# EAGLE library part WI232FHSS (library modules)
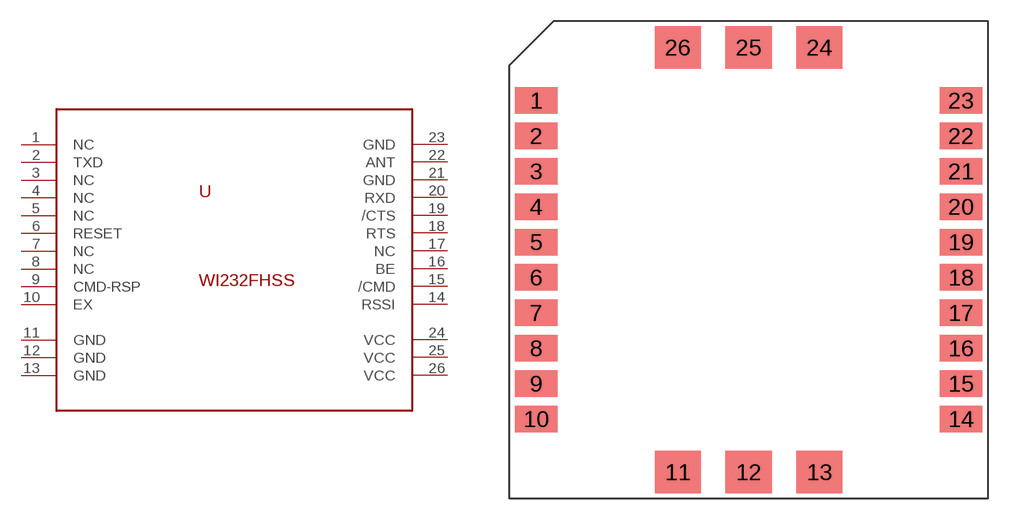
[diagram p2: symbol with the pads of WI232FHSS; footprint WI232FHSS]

Designator prefix U

## WI232FHSS  [WI232FHSS]
1  NC  nc
2  TXD  out
3  NC  nc
4  NC  nc
5  NC  nc
6  RESET  in
7  NC  nc
8  NC  nc
9  CMD-RSP  out
10  EX  out
11  GND  pwr
12  GND  pwr
13  GND  pwr
14  RSSI  out
15  /CMD  in
16  BE  out
17  NC  nc
18  RTS  in
19  /CTS  out
20  RXD  in
21  GND  pwr
22  ANT  out
23  GND  pwr
24  VCC  pwr
25  VCC  pwr
26  VCC  pwr

## Footprint WI232FHSS (pad centres in mm)
smd 3.048 x 1.905: 1 -15.24,11.43; 2 -15.24,8.89; 3 -15.24,6.35; 4 -15.24,3.81; 5 -15.24,1.27; 6 -15.24,-1.27; 7 -15.24,-3.81; 8 -15.24,-6.35; 9 -15.24,-8.89; 10 -15.24,-11.43; 14 15.24,-11.43; 15 15.24,-8.89; 16 15.24,-6.35; 17 15.24,-3.81; 18 15.24,-1.27; 19 15.24,1.27; 20 15.24,3.81; 21 15.24,6.35; 22 15.24,8.89; 23 15.24,11.43
smd 3.302 x 3.048: 11 -5.08,-15.24; 12 0,-15.24; 13 5.08,-15.24; 24 5.08,15.24; 25 0,15.24; 26 -5.08,15.24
